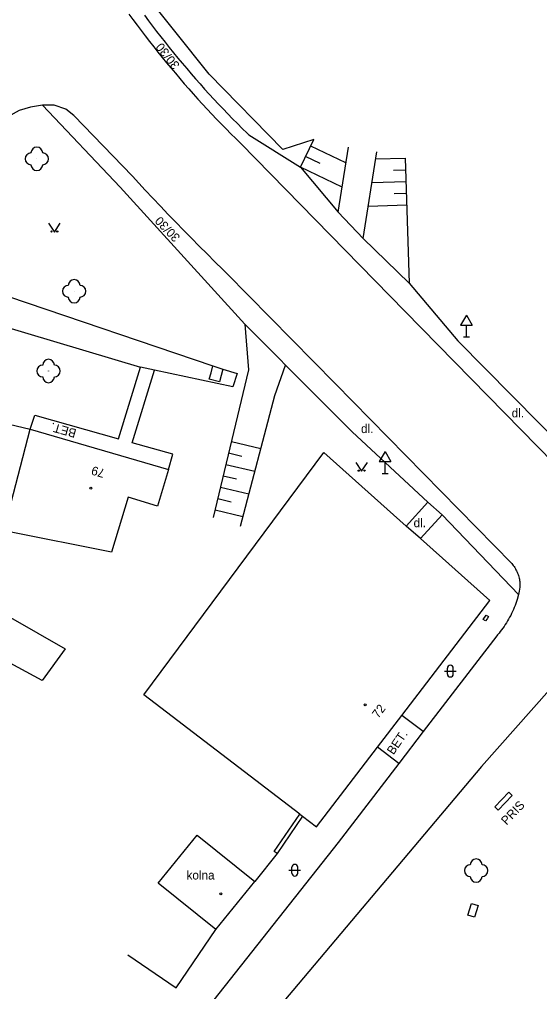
# Model space of a CAD drawing. Extents: x -544674 to -541478, y -1199076 to -1195527.
# Drawn here: x -543839.4 to -543795, y -1197417 to -1197333.9 of the extents above; entities that cross this region are included whole.
import ezdxf

# ---------------------------------------------------------------- set-up
doc = ezdxf.new("R2010")
doc.units = 0
for name, color, linetype in [('BUDOVY_MĚŘ', 7, 'Continuous'), ('BUDOVY_NEMĚŘ', 7, 'Continuous'), ('OBVOD_PILÍŘE', 7, 'Continuous'), ('POMOC_POPIS', 7, 'Continuous'), ('ROZHRANÍ_PLOCH', 7, 'Continuous'), ('VÝŠKOPIS', 7, 'Continuous'), ('ZELEŇ', 7, 'Continuous'), ('ZN_BUDOV', 7, 'Continuous'), ('ZN_DOPLŇKOVÉ', 7, 'Continuous'), ('ZN_KULTUR', 7, 'Continuous'), ('Č_POPIS_ORIENT', 7, 'Continuous')]:
    doc.layers.add(name, color=color, linetype=linetype)

msp = doc.modelspace()

# ---------------------------------------------------------------- linework, layer by layer
at = {"layer": 'BUDOVY_MĚŘ'}
for points in [[(-543850.21, -1197379.21), (-543849.93, -1197373.89), (-543847.97, -1197366.69), (-543838.51, -1197368.93)], [(-543840.76, -1197377.61), (-543838.51, -1197368.93)], [(-543838.51, -1197368.93), (-543826.69, -1197372.36)], [(-543806.36, -1197377.21), (-543813.41, -1197370.93)], [(-543826.69, -1197372.36), (-543827.62, -1197375.49)], [(-543805.16, -1197378.27), (-543806.36, -1197377.21)], [(-543814.04, -1197402.89), (-543808.83, -1197396.1), (-543806.74, -1197393.37), (-543799.22, -1197383.56), (-543805.16, -1197378.27)], [(-543815.47, -1197401.8), (-543815.23, -1197401.98)], [(-543815.23, -1197401.98), (-543814.04, -1197402.89)], [(-543822.63, -1197411.67), (-543819.31, -1197407.57)]]:
    msp.add_lwpolyline(points, dxfattribs=at)
at = {"layer": 'BUDOVY_NEMĚŘ'}
for points in [[(-543815.47, -1197401.8), (-543828.79, -1197391.62), (-543813.41, -1197370.93)], [(-543827.62, -1197375.49), (-543830.13, -1197374.74), (-543831.54, -1197379.44), (-543840.4, -1197377.66)], [(-543840.18, -1197385.01), (-543835.52, -1197387.68), (-543837.48, -1197390.38), (-543840.9, -1197388.53), (-543842.28, -1197391.08), (-543846.85, -1197388.6), (-543850.85, -1197395.99), (-543852.24, -1197395.14)], [(-543822.63, -1197411.67), (-543827.56, -1197407.7), (-543824.23, -1197403.59), (-543819.31, -1197407.57)]]:
    msp.add_lwpolyline(points, dxfattribs=at)
at = {"layer": 'OBVOD_PILÍŘE'}
for points in [[(-543799.53, -1197384.8), (-543799.33, -1197384.94), (-543799.46, -1197385.12), (-543799.59, -1197385.31), (-543799.79, -1197385.17), (-543799.53, -1197384.8)], [(-543801.1, -1197410.43), (-543800.79, -1197409.43), (-543800.22, -1197409.61), (-543800.54, -1197410.61), (-543801.1, -1197410.43)]]:
    msp.add_lwpolyline(points, dxfattribs=at)
at = {"layer": 'ROZHRANÍ_PLOCH'}
for points in [[(-543830.06, -1197333.47), (-543829.72, -1197333.94), (-543829.37, -1197334.41), (-543829.02, -1197334.88), (-543828.66, -1197335.34), (-543828.31, -1197335.81), (-543827.94, -1197336.27), (-543827.58, -1197336.72), (-543827.21, -1197337.18), (-543826.84, -1197337.63), (-543826.47, -1197338.08), (-543826.09, -1197338.53), (-543825.72, -1197338.98), (-543825.33, -1197339.42), (-543824.95, -1197339.86), (-543824.56, -1197340.3), (-543824.17, -1197340.73), (-543823.77, -1197341.16), (-543823.38, -1197341.59), (-543822.98, -1197342.02), (-543822.57, -1197342.44), (-543822.17, -1197342.86), (-543821.76, -1197343.28), (-543821.35, -1197343.69), (-543820.93, -1197344.11), (-543820.51, -1197344.52), (-543806.49, -1197358.84)], [(-543828.74, -1197333.58), (-543828.4, -1197334.04), (-543828.04, -1197334.51), (-543827.69, -1197334.97), (-543827.33, -1197335.43), (-543826.97, -1197335.88), (-543826.61, -1197336.34), (-543826.24, -1197336.79), (-543825.87, -1197337.24), (-543825.5, -1197337.68), (-543825.12, -1197338.13), (-543824.75, -1197338.57), (-543824.36, -1197339.01), (-543823.98, -1197339.44), (-543823.59, -1197339.88), (-543823.2, -1197340.31), (-543822.81, -1197340.73), (-543822.41, -1197341.16), (-543822.01, -1197341.58), (-543821.61, -1197342), (-543821.2, -1197342.42), (-543820.79, -1197342.83), (-543820.38, -1197343.24), (-543819.97, -1197343.65), (-543819.81, -1197343.8), (-543815.39, -1197346.55), (-543812.17, -1197350.38), (-543810.04, -1197352.65), (-543806.11, -1197356.46), (-543801.97, -1197361.38)], [(-543837.45, -1197341.26), (-543838.48, -1197341.42), (-543839.45, -1197341.71), (-543840.42, -1197342.25), (-543841.16, -1197342.95), (-543841.83, -1197343.96), (-543844.38, -1197352.14), (-543844.51, -1197353.26), (-543844.31, -1197354.29), (-543843.88, -1197355.31), (-543843.42, -1197356.12), (-543842.57, -1197356.92), (-543840.34, -1197357.6)], [(-543829.75, -1197347.33), (-543834.77, -1197342.13), (-543835.46, -1197341.59), (-543836.44, -1197341.25), (-543837.45, -1197341.26)], [(-543830.8, -1197348.26), (-543837.45, -1197341.26)], [(-543829.75, -1197347.33), (-543828.67, -1197348.51), (-543828.02, -1197349.2), (-543827.37, -1197349.89), (-543826.71, -1197350.58), (-543826.05, -1197351.26), (-543825.39, -1197351.94), (-543824.72, -1197352.62), (-543824.05, -1197353.29), (-543823.38, -1197353.96), (-543822.71, -1197354.63), (-543822.03, -1197355.3), (-543821.7, -1197355.62)], [(-543820.17, -1197359.97), (-543830.8, -1197348.26)], [(-543821.7, -1197355.62), (-543812.45, -1197365.04)], [(-543840.34, -1197357.6), (-543822.89, -1197363.51)], [(-543806.49, -1197358.84), (-543793.74, -1197371.85)], [(-543841.19, -1197360.01), (-543829.06, -1197363.63)], [(-543813.69, -1197366.44), (-543820.17, -1197359.97)], [(-543801.97, -1197361.38), (-543792.66, -1197370.77), (-543791.44, -1197371.52), (-543790.35, -1197371.59), (-543788.98, -1197371.19), (-543787.62, -1197369.5)], [(-543838.51, -1197368.93), (-543838.09, -1197367.74), (-543830.94, -1197369.75), (-543829.06, -1197363.63)], [(-543826.69, -1197372.36), (-543826.32, -1197371.05), (-543829.79, -1197370.1), (-543827.88, -1197363.88)], [(-543827.88, -1197363.88), (-543829.06, -1197363.63)], [(-543822.03, -1197363.79), (-543820.81, -1197364.17), (-543821.18, -1197365.32), (-543827.88, -1197363.88)], [(-543822.03, -1197363.79), (-543822.32, -1197364.89), (-543823.19, -1197364.66), (-543823.04, -1197364.11), (-543822.89, -1197363.51)], [(-543822.89, -1197363.51), (-543822.03, -1197363.79)], [(-543812.45, -1197365.04), (-543797.35, -1197380.41), (-543797.28, -1197380.49), (-543797.22, -1197380.58), (-543797.15, -1197380.66), (-543797.09, -1197380.75), (-543797.04, -1197380.85), (-543796.99, -1197380.94), (-543796.94, -1197381.03)], [(-543804.53, -1197375.15), (-543810.99, -1197369.15), (-543813.69, -1197366.44), (-543813.74, -1197366.39)], [(-543806.36, -1197377.21), (-543804.53, -1197375.15)], [(-543804.53, -1197375.15), (-543803.3, -1197376.23)], [(-543805.16, -1197378.27), (-543803.3, -1197376.23)], [(-543796.77, -1197383.06), (-543803.3, -1197376.23)], [(-543796.94, -1197381.03), (-543796.89, -1197381.13), (-543796.85, -1197381.23), (-543796.81, -1197381.33), (-543796.78, -1197381.43), (-543796.75, -1197381.53), (-543796.72, -1197381.64), (-543796.7, -1197381.74), (-543796.68, -1197381.85), (-543796.67, -1197381.95), (-543796.66, -1197382.06), (-543796.65, -1197382.17), (-543796.65, -1197382.27), (-543796.65, -1197382.41), (-543796.68, -1197382.59), (-543796.72, -1197382.77), (-543796.77, -1197383.06)], [(-543796.77, -1197383.06), (-543796.9, -1197383.48), (-543796.95, -1197383.65), (-543797.01, -1197383.82), (-543797.07, -1197383.99), (-543797.14, -1197384.16), (-543797.21, -1197384.33), (-543797.29, -1197384.5), (-543797.36, -1197384.66), (-543797.44, -1197384.83), (-543797.53, -1197384.99), (-543797.62, -1197385.15), (-543797.71, -1197385.31), (-543797.8, -1197385.46), (-543797.9, -1197385.62), (-543798, -1197385.77), (-543798.11, -1197385.92), (-543798.22, -1197386.06), (-543798.33, -1197386.21), (-543798.44, -1197386.35), (-543798.56, -1197386.49), (-543798.64, -1197386.58)], [(-543798.64, -1197386.58), (-543804.92, -1197394.76)], [(-543794.12, -1197391.19), (-543799.94, -1197397.74)], [(-543804.92, -1197394.76), (-543806.74, -1197393.37)], [(-543804.92, -1197394.76), (-543807.01, -1197397.49)], [(-543807.01, -1197397.49), (-543808.83, -1197396.1)], [(-543807.01, -1197397.49), (-543812.18, -1197404.22), (-543824.2, -1197419.43), (-543825.96, -1197421.78)], [(-543799.94, -1197397.74), (-543819.57, -1197421.04), (-543823.21, -1197425.87)]]:
    msp.add_lwpolyline(points, dxfattribs=at)
at = {"layer": 'VÝŠKOPIS'}
for points in [[(-543811.52, -1197346.19), (-543814.53, -1197344.75)], [(-543813.73, -1197346.24), (-543814.96, -1197345.65)], [(-543808.99, -1197345.85), (-543806.45, -1197345.77)], [(-543811.84, -1197348.25), (-543815.39, -1197346.55)], [(-543807.45, -1197346.8), (-543806.42, -1197346.77)], [(-543809.3, -1197347.86), (-543806.39, -1197347.77)], [(-543807.39, -1197348.8), (-543806.35, -1197348.77)], [(-543809.61, -1197349.87), (-543806.32, -1197349.77)], [(-543818.79, -1197370.61), (-543821.31, -1197370.01)], [(-543820.4, -1197371.25), (-543821.54, -1197370.98)], [(-543819.31, -1197372.54), (-543821.78, -1197371.96)], [(-543820.86, -1197373.2), (-543822.01, -1197372.93)], [(-543819.82, -1197374.48), (-543822.24, -1197373.9)], [(-543821.33, -1197375.15), (-543822.47, -1197374.87)], [(-543820.33, -1197376.41), (-543822.7, -1197375.85)]]:
    msp.add_lwpolyline(points, dxfattribs=at)
at = {"layer": 'ZELEŇ'}
for centre in [(-543837.93, -1197345.84), (-543834.74, -1197357.15), (-543836.93, -1197363.96), (-543800.39, -1197406.63)]:
    msp.add_circle(centre, 0.0005, dxfattribs=at)
for centre, start, end in [((-543837.93, -1197345.34), 0, 179.99999), ((-543838.43, -1197345.84), 89.99999, 269.99999), ((-543837.43, -1197345.84), 270, 89.99999), ((-543837.93, -1197346.34), 179.99999, 359.99999), ((-543835.24, -1197357.15), 90, 269.99999), ((-543834.74, -1197356.65), 360, 179.99999), ((-543834.24, -1197357.15), 270, 90), ((-543834.74, -1197357.65), 180, 360), ((-543836.93, -1197363.46), 0, 179.99999), ((-543837.43, -1197363.96), 89.99999, 269.99999), ((-543836.43, -1197363.96), 270, 89.99999), ((-543836.93, -1197364.46), 179.99999, 359.99999), ((-543800.39, -1197406.13), 0, 179.99999), ((-543800.89, -1197406.63), 89.99999, 269.99999), ((-543799.89, -1197406.63), 270, 89.99999), ((-543800.39, -1197407.13), 179.99999, 359.99999)]:
    msp.add_arc(centre, 0.5, start, end, dxfattribs=at)
at = {"layer": 'ZN_BUDOV'}
for centre in [(-543833.31, -1197373.97), (-543809.87, -1197392.48), (-543822.2, -1197408.61)]:
    msp.add_circle(centre, 0.0875, dxfattribs=at)
at = {"layer": 'ZN_DOPLŇKOVÉ'}
for p, q in [((-543801.22, -1197359.184), (-543801.72, -1197360.05)), ((-543801.22, -1197359.184), (-543800.72, -1197360.05)), ((-543801.72, -1197360.05), (-543800.72, -1197360.05)), ((-543801.22, -1197361.05), (-543801.22, -1197360.05)), ((-543801.47, -1197361.05), (-543800.97, -1197361.05)), ((-543808.17, -1197370.834), (-543808.67, -1197371.7)), ((-543808.17, -1197370.834), (-543807.67, -1197371.7)), ((-543808.67, -1197371.7), (-543807.67, -1197371.7)), ((-543808.17, -1197372.7), (-543808.17, -1197371.7)), ((-543808.42, -1197372.7), (-543807.92, -1197372.7))]:
    msp.add_line(p, q, dxfattribs=at)
for points in [[(-543814.26, -1197344.19), (-543816.92, -1197345.05), (-543823.2, -1197338.62), (-543832.01, -1197327.55), (-543833.87, -1197324.49), (-543835.24, -1197320.94)], [(-543815.39, -1197346.55), (-543814.26, -1197344.19)], [(-543812.17, -1197350.38), (-543811.31, -1197344.85)], [(-543810.04, -1197352.65), (-543808.89, -1197345.23)], [(-543806.45, -1197345.77), (-543806.11, -1197356.46)], [(-543820.17, -1197359.97), (-543819.85, -1197363.85), (-543822.85, -1197376.47)], [(-543817.59, -1197366.05), (-543816.69, -1197363.45)], [(-543820.54, -1197377.2), (-543817.59, -1197366.05)], [(-543798.81, -1197401.18), (-543797.6, -1197399.94), (-543797.31, -1197400.22), (-543798.52, -1197401.46), (-543798.81, -1197401.18)], [(-543817.4, -1197405.17), (-543817.65, -1197405), (-543815.47, -1197401.8)], [(-543815.23, -1197401.98), (-543817.4, -1197405.17)], [(-543817.4, -1197405.17), (-543819.31, -1197407.57)], [(-543830.15, -1197413.82), (-543826.02, -1197416.64), (-543822.63, -1197411.67)]]:
    msp.add_lwpolyline(points, dxfattribs=at)
at = {"layer": 'ZN_KULTUR'}
for p, q in [((-543803.1, -1197389.59), (-543802.1, -1197389.59)), ((-543802.85, -1197389.84), (-543802.85, -1197389.34)), ((-543802.35, -1197389.84), (-543802.35, -1197389.34)), ((-543816.14, -1197406.85), (-543816.14, -1197406.35)), ((-543815.64, -1197406.85), (-543815.64, -1197406.35)), ((-543816.39, -1197406.6), (-543815.39, -1197406.6))]:
    msp.add_line(p, q, dxfattribs=at)
for points in [[(-543836.93, -1197351.34), (-543836.43, -1197352.09), (-543835.93, -1197351.34)], [(-543810.68, -1197371.77), (-543810.18, -1197372.52), (-543809.68, -1197371.77)]]:
    msp.add_lwpolyline(points, dxfattribs=at)
for centre in [(-543836.68, -1197352.04), (-543836.18, -1197352.04), (-543810.43, -1197372.47), (-543809.93, -1197372.47)]:
    msp.add_circle(centre, 0.05, dxfattribs=at)
for centre, start, end in [((-543802.6, -1197389.34), 0, 179.99999), ((-543802.6, -1197389.84), 179.99999, 359.99999), ((-543815.89, -1197406.35), 0, 179.99999), ((-543815.89, -1197406.85), 179.99999, 359.99999)]:
    msp.add_arc(centre, 0.25, start, end, dxfattribs=at)

# ---------------------------------------------------------------- texts
at = {"layer": 'POMOC_POPIS'}
for s, rotation, p in [('30/30', 128.57001, (-543825.68, -1197337.82)), ('30/30', 133.84999, (-543825.63, -1197352.5)), ('BET.', 164.3, (-543834.49, -1197368.96)), ('BET.', 55.63999, (-543807.46, -1197396.79)), ('PRIS', 46.31, (-543797.8, -1197402.79))]:
    msp.add_text(s, height=0.75, rotation=rotation, dxfattribs=at).set_placement(p)
for s, p in [('dl.', (-543797.36, -1197367.92)), ('dl.', (-543810.23, -1197369.26)), ('dl.', (-543805.74, -1197377.3)), ('kolna', (-543825.14, -1197407.39))]:
    msp.add_text(s, height=0.75, dxfattribs=at).set_placement(p)
at = {"layer": 'Č_POPIS_ORIENT'}
for s, rotation, p in [('79', 163.81998, (-543832.06, -1197372.38)), ('72', 52.61002, (-543808.76, -1197393.68))]:
    msp.add_text(s, height=0.75, rotation=rotation, dxfattribs=at).set_placement(p)

doc.saveas('drawing.dxf')
